(* Logix 5000 project; controller PDPMV1_60_v15 vendor 1 type 14 code 65 rev 15.1; software revision 15.00; part 2 of 3 *)
(* tags used below, declared in another part *)
   MVI69PDPMV1 : PDPMV1_ModuleDef;
(* MainProgram, continued *)

ROUTINE MainRoutine   (* ladder *)
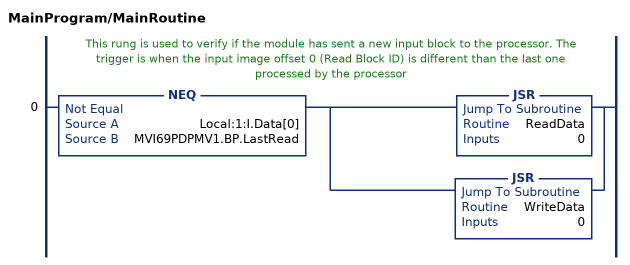
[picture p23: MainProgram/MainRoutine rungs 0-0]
   // This rung is used to verify if the module has sent a new input block to the processor. The trigger is when the input image offset 0 (Read Block ID) is different than the last one processed by the processor
   0: NEQ(Local:1:I.Data[0],MVI69PDPMV1.BP.LastRead)[JSR(ReadData,0) ,JSR(WriteData,0) ];
END_ROUTINE

ROUTINE ReadAlarm   (* ladder *)
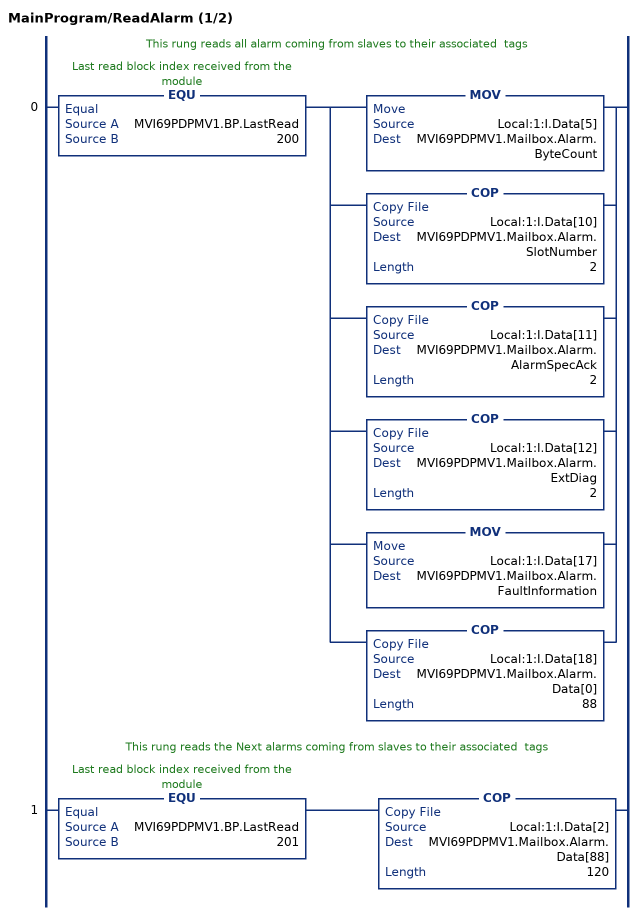
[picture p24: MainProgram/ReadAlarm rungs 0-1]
   // This rung reads all alarm coming from slaves to their associated  tags
   0: EQU(MVI69PDPMV1.BP.LastRead,200)[MOV(Local:1:I.Data[5],MVI69PDPMV1.Mailbox.Alarm.ByteCount) ,COP(Local:1:I.Data[10],MVI69PDPMV1.Mailbox.Alarm.SlotNumber,2) ,COP(Local:1:I.Data[11],MVI69PDPMV1.Mailbox.Alarm.AlarmSpecAck,2) ,COP(Local:1:I.Data[12],MVI69PDPMV1.Mailbox.Alarm.ExtDiag,2) ,MOV(Local:1:I.Data[17],MVI69PDPMV1.Mailbox.Alarm.FaultInformation) ,COP(Local:1:I.Data[18],MVI69PDPMV1.Mailbox.Alarm.Data[0],88) ];
   // This rung reads the Next alarms coming from slaves to their associated  tags
   1: EQU(MVI69PDPMV1.BP.LastRead,201)COP(Local:1:I.Data[2],MVI69PDPMV1.Mailbox.Alarm.Data[88],120);
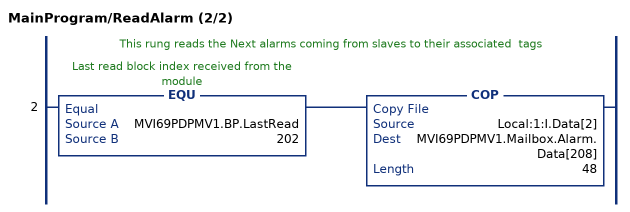
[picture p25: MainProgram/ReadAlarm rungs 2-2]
   // This rung reads the Next alarms coming from slaves to their associated  tags
   2: EQU(MVI69PDPMV1.BP.LastRead,202)COP(Local:1:I.Data[2],MVI69PDPMV1.Mailbox.Alarm.Data[208],48);
END_ROUTINE

ROUTINE ReadData   (* ladder *)
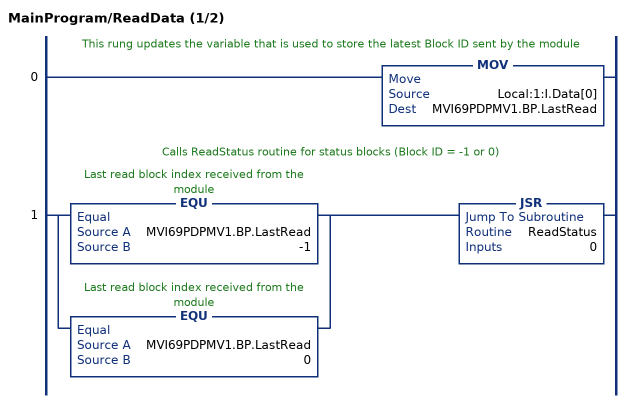
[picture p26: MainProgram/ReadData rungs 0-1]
   // This rung updates the variable that is used to store the latest Block ID sent by the module
   0: MOV(Local:1:I.Data[0],MVI69PDPMV1.BP.LastRead);
   // Calls ReadStatus routine for status blocks (Block ID = -1 or 0)
   1: [EQU(MVI69PDPMV1.BP.LastRead,-1) ,EQU(MVI69PDPMV1.BP.LastRead,0) ]JSR(ReadStatus,0);
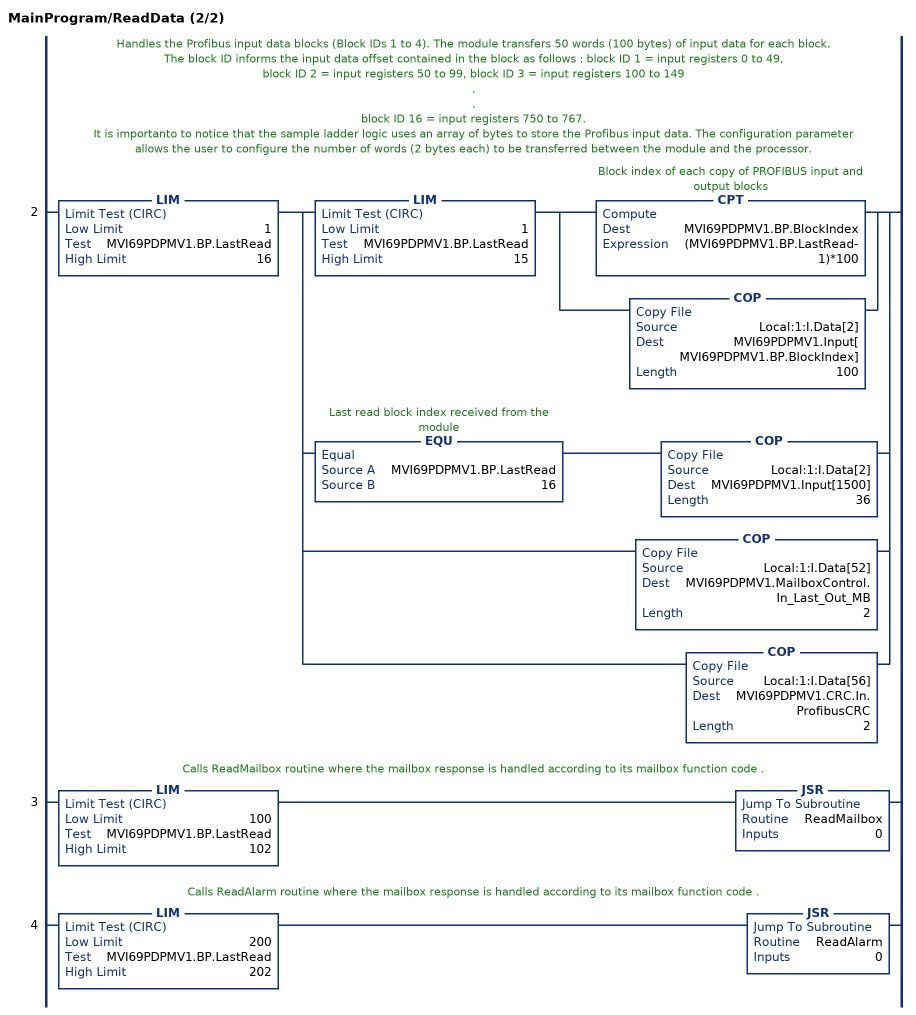
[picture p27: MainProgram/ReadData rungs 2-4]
   // Handles the Profibus input data blocks (Block IDs 1 to 4). The module transfers 50 words (100 bytes) of input data for each block.
   // The block ID informs the input data offset contained in the block as follows : block ID 1 = input registers 0 to 49,
   // block ID 2 = input registers 50 to 99, block ID 3 = input registers 100 to 149
   // .
   // .
   // block ID 16 = input registers 750 to 767.
   // It is importanto to notice that the sample ladder logic uses an array of bytes to store the Profibus input data. The configuration parameter allows the user to configure the number of words (2 bytes each) to be transferred between the module and the processor.
   2: LIM(1,MVI69PDPMV1.BP.LastRead,16)[LIM(1,MVI69PDPMV1.BP.LastRead,15) [CPT(MVI69PDPMV1.BP.BlockIndex,(MVI69PDPMV1.BP.LastRead-1)*100) ,COP(Local:1:I.Data[2],MVI69PDPMV1.Input[MVI69PDPMV1.BP.BlockIndex],100) ] ,EQU(MVI69PDPMV1.BP.LastRead,16) COP(Local:1:I.Data[2],MVI69PDPMV1.Input[1500],36) ,COP(Local:1:I.Data[52],MVI69PDPMV1.MailboxControl.In_Last_Out_MB,2) ,COP(Local:1:I.Data[56],MVI69PDPMV1.CRC.In.ProfibusCRC,2) ];
   // Calls ReadMailbox routine where the mailbox response is handled according to its mailbox function code .
   3: LIM(100,MVI69PDPMV1.BP.LastRead,102)JSR(ReadMailbox,0);
   // Calls ReadAlarm routine where the mailbox response is handled according to its mailbox function code .
   4: LIM(200,MVI69PDPMV1.BP.LastRead,202)JSR(ReadAlarm,0);
END_ROUTINE

ROUTINE ReadMailbox   (* ladder *)
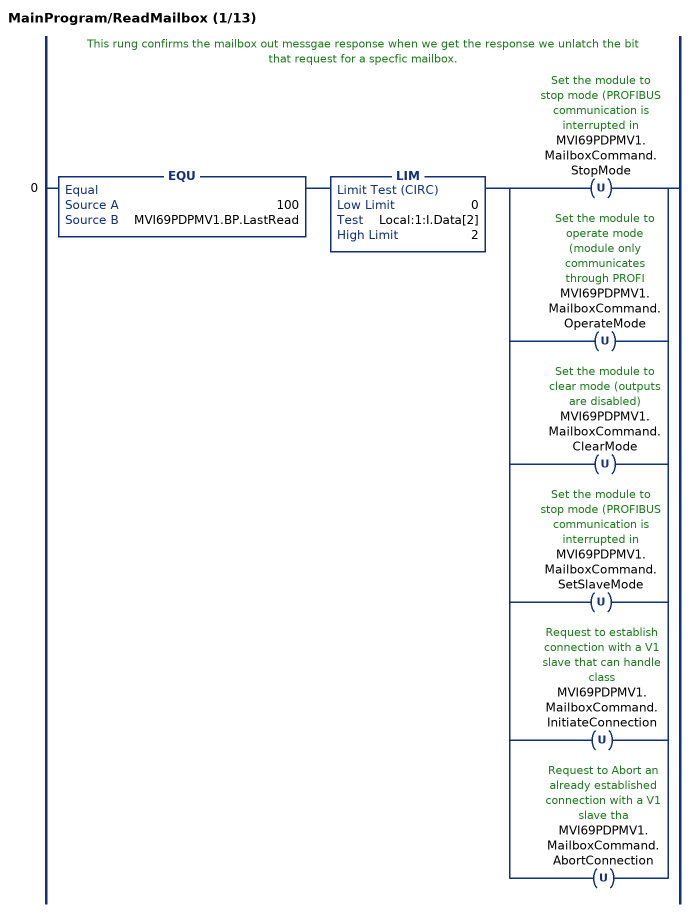
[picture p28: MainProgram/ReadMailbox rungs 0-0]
   // This rung confirms the mailbox out messgae response when we get the response we unlatch the bit that request for a specfic mailbox.
   0: EQU(100,MVI69PDPMV1.BP.LastRead)LIM(0,Local:1:I.Data[2],2)[OTU(MVI69PDPMV1.MailboxCommand.StopMode) ,OTU(MVI69PDPMV1.MailboxCommand.OperateMode) ,OTU(MVI69PDPMV1.MailboxCommand.ClearMode) ,OTU(MVI69PDPMV1.MailboxCommand.SetSlaveMode) ,OTU(MVI69PDPMV1.MailboxCommand.InitiateConnection) ,OTU(MVI69PDPMV1.MailboxCommand.AbortConnection) ];
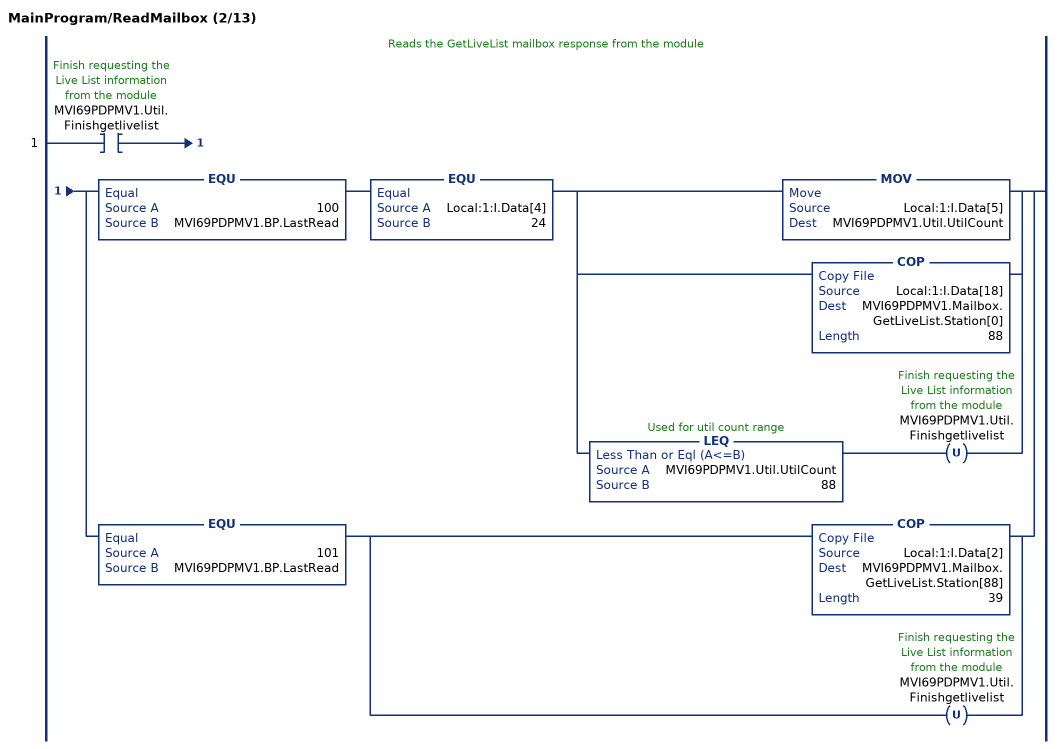
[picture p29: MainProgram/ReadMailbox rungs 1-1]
   // Reads the GetLiveList mailbox response from the module
   1: XIC(MVI69PDPMV1.Util.Finishgetlivelist)[EQU(100,MVI69PDPMV1.BP.LastRead) EQU(Local:1:I.Data[4],24) [MOV(Local:1:I.Data[5],MVI69PDPMV1.Util.UtilCount) ,COP(Local:1:I.Data[18],MVI69PDPMV1.Mailbox.GetLiveList.Station[0],88) ,LEQ(MVI69PDPMV1.Util.UtilCount,88) OTU(MVI69PDPMV1.Util.Finishgetlivelist) ] ,EQU(101,MVI69PDPMV1.BP.LastRead) [COP(Local:1:I.Data[2],MVI69PDPMV1.Mailbox.GetLiveList.Station[88],39) ,OTU(MVI69PDPMV1.Util.Finishgetlivelist) ] ];
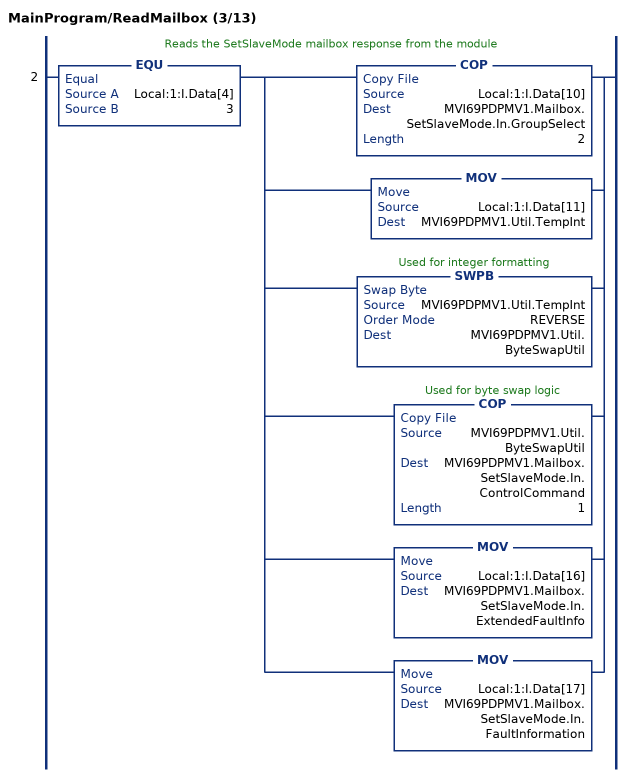
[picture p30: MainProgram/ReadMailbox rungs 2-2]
   // Reads the SetSlaveMode mailbox response from the module
   2: EQU(Local:1:I.Data[4],3)[COP(Local:1:I.Data[10],MVI69PDPMV1.Mailbox.SetSlaveMode.In.GroupSelect,2) ,MOV(Local:1:I.Data[11],MVI69PDPMV1.Util.TempInt) ,SWPB(MVI69PDPMV1.Util.TempInt,REVERSE,MVI69PDPMV1.Util.ByteSwapUtil) ,COP(MVI69PDPMV1.Util.ByteSwapUtil,MVI69PDPMV1.Mailbox.SetSlaveMode.In.ControlCommand,1) ,MOV(Local:1:I.Data[16],MVI69PDPMV1.Mailbox.SetSlaveMode.In.ExtendedFaultInfo) ,MOV(Local:1:I.Data[17],MVI69PDPMV1.Mailbox.SetSlaveMode.In.FaultInformation) ];
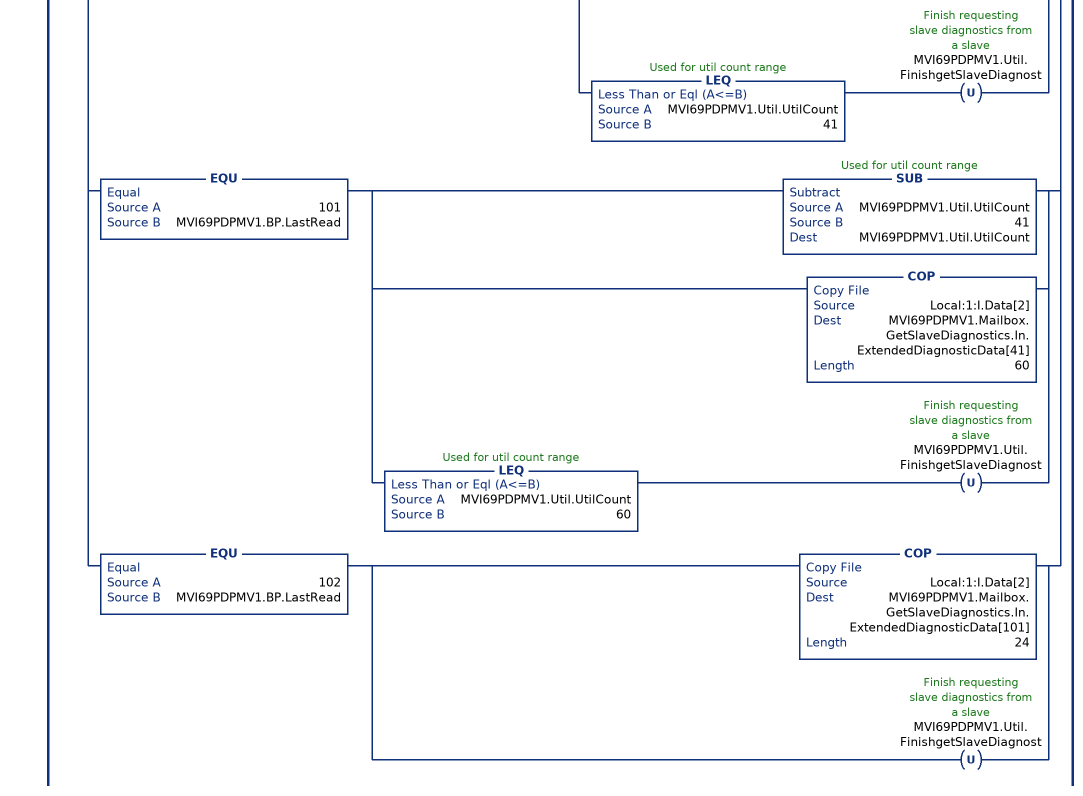
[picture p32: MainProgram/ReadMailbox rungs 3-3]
   // Reads the GetSlaveDiagnostics mailbox response from the module
   3: XIC(MVI69PDPMV1.Util.FinishgetSlaveDiagnost)[EQU(100,MVI69PDPMV1.BP.LastRead) EQU(Local:1:I.Data[4],4) [MOV(Local:1:I.Data[5],MVI69PDPMV1.Util.UtilCount) ,COP(Local:1:I.Data[10],MVI69PDPMV1.Mailbox.GetSlaveDiagnostics.In.RequestType,2) ,MOV(Local:1:I.Data[16],MVI69PDPMV1.Mailbox.GetSlaveDiagnostics.In.ExtendedFaultInfo) ,MOV(Local:1:I.Data[17],MVI69PDPMV1.Mailbox.GetSlaveDiagnostics.In.FaultInformation) ,MOV(Local:1:I.Data[18],MVI69PDPMV1.Mailbox.GetSlaveDiagnostics.In.StationStatus1_2) ,MOV(Local:1:I.Data[19],MVI69PDPMV1.Mailbox.GetSlaveDiagnostics.In.StationStatus3_4) ,MOV(Local:1:I.Data[20],MVI69PDPMV1.Mailbox.GetSlaveDiagnostics.In.IdentNumber) ,COP(Local:1:I.Data[21],MVI69PDPMV1.Mailbox.GetSlaveDiagnostics.In.ExtendedDiagnosticData[0],41) ,LEQ(MVI69PDPMV1.Util.UtilCount,41) OTU(MVI69PDPMV1.Util.FinishgetSlaveDiagnost) ] ,EQU(101,MVI69PDPMV1.BP.LastRead) [SUB(MVI69PDPMV1.Util.UtilCount,41,MVI69PDPMV1.Util.UtilCount) ,COP(Local:1:I.Data[2],MVI69PDPMV1.Mailbox.GetSlaveDiagnostics.In.ExtendedDiagnosticData[41],60) ,LEQ(MVI69PDPMV1.Util.UtilCount,60) OTU(MVI69PDPMV1.Util.FinishgetSlaveDiagnost) ] ,EQU(102,MVI69PDPMV1.BP.LastRead) [COP(Local:1:I.Data[2],MVI69PDPMV1.Mailbox.GetSlaveDiagnostics.In.ExtendedDiagnosticData[101],24) ,OTU(MVI69PDPMV1.Util.FinishgetSlaveDiagnost) ] ];
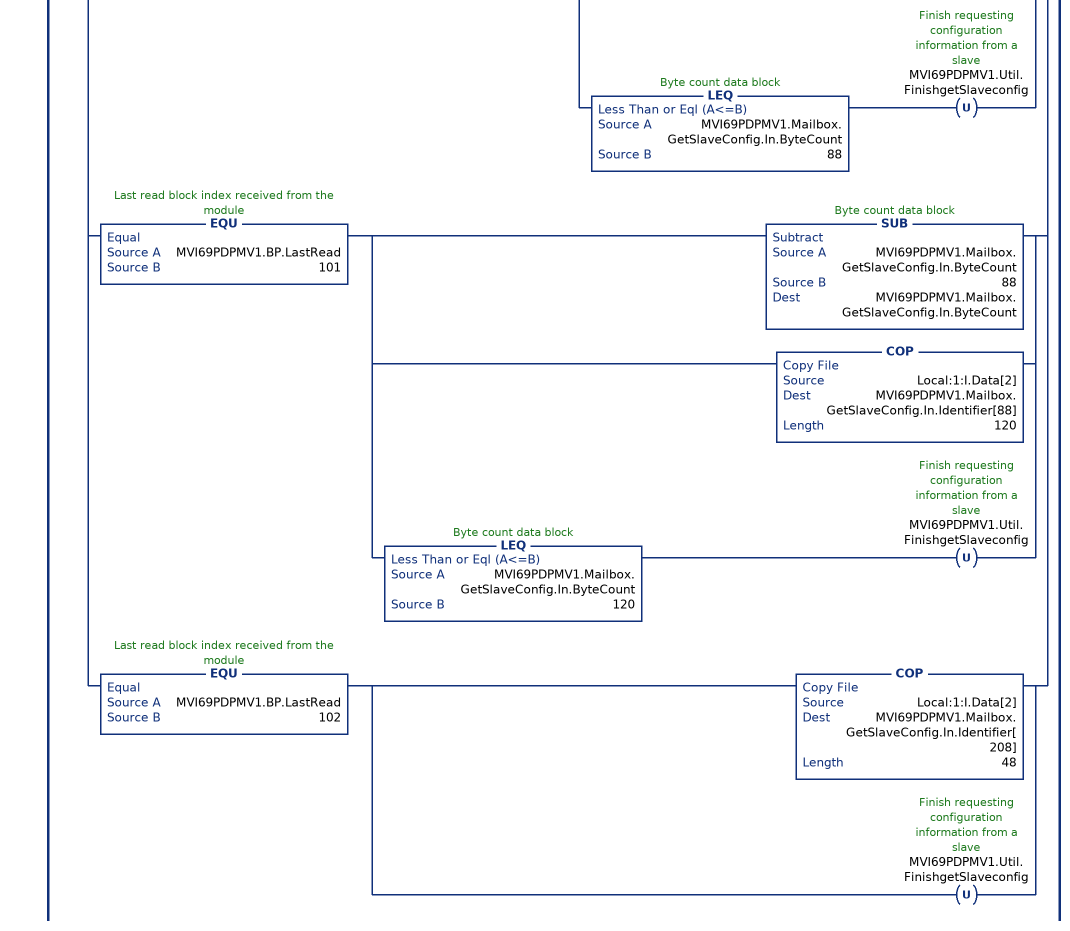
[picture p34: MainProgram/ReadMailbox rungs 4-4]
   // Reads the GetSlaveConfig mailbox response from the module
   4: XIC(MVI69PDPMV1.Util.FinishgetSlaveconfig)[EQU(MVI69PDPMV1.BP.LastRead,100) EQU(Local:1:I.Data[4],5) [MOV(Local:1:I.Data[5],MVI69PDPMV1.Mailbox.GetSlaveConfig.In.ByteCount) ,MOV(Local:1:I.Data[10],MVI69PDPMV1.Util.ByteSwapUtil) ,SWPB(MVI69PDPMV1.Util.ByteSwapUtil,REVERSE,MVI69PDPMV1.Mailbox.GetSlaveConfig.In.SlaveAddress) ,COP(Local:1:I.Data[14],MVI69PDPMV1.Mailbox.GetSlaveConfig.In.ErrorCode[0],2) ,MOV(Local:1:I.Data[16],MVI69PDPMV1.Mailbox.GetSlaveConfig.In.ReturnCode) ,MOV(Local:1:I.Data[17],MVI69PDPMV1.Mailbox.GetSlaveConfig.In.FaultInformation) ,COP(Local:1:I.Data[18],MVI69PDPMV1.Mailbox.GetSlaveConfig.In.Identifier[0],88) ,LEQ(MVI69PDPMV1.Mailbox.GetSlaveConfig.In.ByteCount,88) OTU(MVI69PDPMV1.Util.FinishgetSlaveconfig) ] ,EQU(MVI69PDPMV1.BP.LastRead,101) [SUB(MVI69PDPMV1.Mailbox.GetSlaveConfig.In.ByteCount,88,MVI69PDPMV1.Mailbox.GetSlaveConfig.In.ByteCount) ,COP(Local:1:I.Data[2],MVI69PDPMV1.Mailbox.GetSlaveConfig.In.Identifier[88],120) ,LEQ(MVI69PDPMV1.Mailbox.GetSlaveConfig.In.ByteCount,120) OTU(MVI69PDPMV1.Util.FinishgetSlaveconfig) ] ,EQU(MVI69PDPMV1.BP.LastRead,102) [COP(Local:1:I.Data[2],MVI69PDPMV1.Mailbox.GetSlaveConfig.In.Identifier[208],48) ,OTU(MVI69PDPMV1.Util.FinishgetSlaveconfig) ] ];
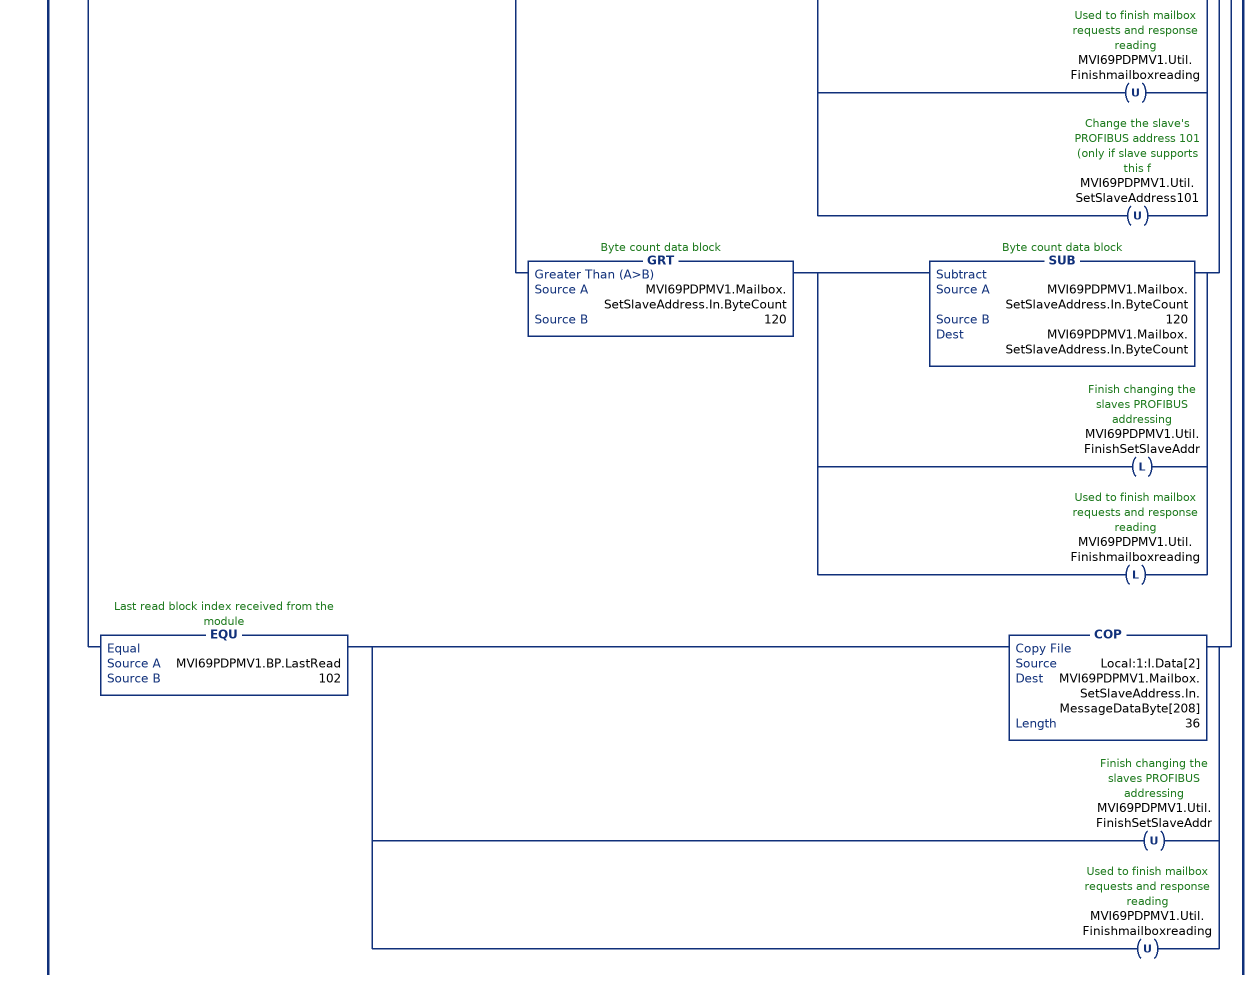
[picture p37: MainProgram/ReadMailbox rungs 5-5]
   // Reads the SetSlaveAddress mailbox response from the module
   5: XIC(MVI69PDPMV1.Util.FinishSetSlaveAddr)[EQU(MVI69PDPMV1.BP.LastRead,100) EQU(Local:1:I.Data[4],6) [MOV(Local:1:I.Data[5],MVI69PDPMV1.Mailbox.SetSlaveAddress.In.ByteCount) ,COP(Local:1:I.Data[10],MVI69PDPMV1.Mailbox.SetSlaveAddress.In.NewSlaveAddress,2) ,MOV(Local:1:I.Data[11],MVI69PDPMV1.Mailbox.SetSlaveAddress.In.SlaveIdentNumber) ,MOV(Local:1:I.Data[12],MVI69PDPMV1.Util.ByteSwapUtil) ,SWPB(MVI69PDPMV1.Util.ByteSwapUtil,REVERSE,MVI69PDPMV1.Mailbox.SetSlaveAddress.In.No_add_Chg) ,MOV(Local:1:I.Data[14],MVI69PDPMV1.Mailbox.SetSlaveAddress.In.ErrorCode1_2) ,MOV(Local:1:I.Data[15],MVI69PDPMV1.Mailbox.SetSlaveAddress.In.ErrorCode3_4) ,MOV(Local:1:I.Data[16],MVI69PDPMV1.Mailbox.SetSlaveAddress.In.ReturnCode) ,MOV(Local:1:I.Data[17],MVI69PDPMV1.Mailbox.SetSlaveAddress.In.FaultInformation) ,COP(Local:1:I.Data[18],MVI69PDPMV1.Mailbox.SetSlaveAddress.In.MessageDataByte[0],88) ,LEQ(MVI69PDPMV1.Mailbox.SetSlaveAddress.In.ByteCount,88) OTU(MVI69PDPMV1.Util.FinishSetSlaveAddr) ,GRT(MVI69PDPMV1.Mailbox.SetSlaveAddress.In.ByteCount,88) [SUB(MVI69PDPMV1.Mailbox.SetSlaveAddress.In.ByteCount,88,MVI69PDPMV1.Mailbox.SetSlaveAddress.In.ByteCount) ,OTL(MVI69PDPMV1.Util.SetSlaveAddress101) ,OTL(MVI69PDPMV1.Util.Finishmailboxreading) ] ] ,EQU(MVI69PDPMV1.BP.LastRead,101) XIC(MVI69PDPMV1.Util.Finishmailboxreading) [LEQ(MVI69PDPMV1.Mailbox.SetSlaveAddress.In.ByteCount,120) [COP(Local:1:I.Data[2],MVI69PDPMV1.Mailbox.SetSlaveAddress.In.MessageDataByte[88],120) ,OTU(MVI69PDPMV1.Util.Finishmailboxreading) ,OTU(MVI69PDPMV1.Util.SetSlaveAddress101) ] ,GRT(MVI69PDPMV1.Mailbox.SetSlaveAddress.In.ByteCount,120) [SUB(MVI69PDPMV1.Mailbox.SetSlaveAddress.In.ByteCount,120,MVI69PDPMV1.Mailbox.SetSlaveAddress.In.ByteCount) ,OTL(MVI69PDPMV1.Util.FinishSetSlaveAddr) ,OTL(MVI69PDPMV1.Util.Finishmailboxreading) ] ] ,EQU(MVI69PDPMV1.BP.LastRead,102) [COP(Local:1:I.Data[2],MVI69PDPMV1.Mailbox.SetSlaveAddress.In.MessageDataByte[208],36) ,OTU(MVI69PDPMV1.Util.FinishSetSlaveAddr) ,OTU(MVI69PDPMV1.Util.Finishmailboxreading) ] ];
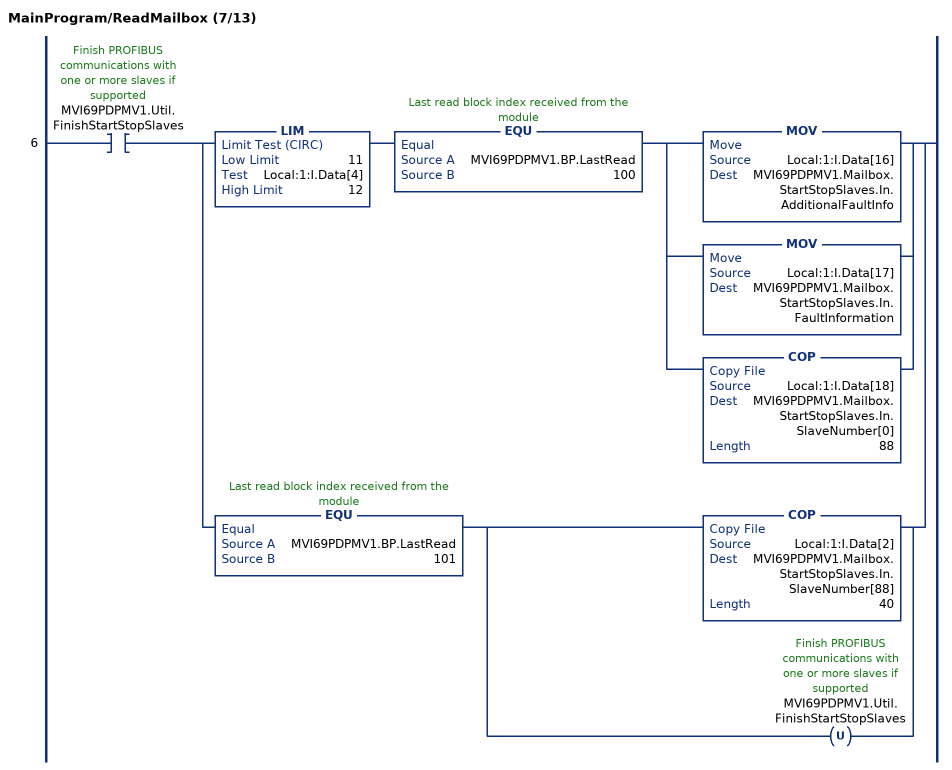
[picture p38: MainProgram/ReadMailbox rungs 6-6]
   6: XIC(MVI69PDPMV1.Util.FinishStartStopSlaves)[LIM(11,Local:1:I.Data[4],12) EQU(MVI69PDPMV1.BP.LastRead,100) [MOV(Local:1:I.Data[16],MVI69PDPMV1.Mailbox.StartStopSlaves.In.AdditionalFaultInfo) ,MOV(Local:1:I.Data[17],MVI69PDPMV1.Mailbox.StartStopSlaves.In.FaultInformation) ,COP(Local:1:I.Data[18],MVI69PDPMV1.Mailbox.StartStopSlaves.In.SlaveNumber[0],88) ] ,EQU(MVI69PDPMV1.BP.LastRead,101) [COP(Local:1:I.Data[2],MVI69PDPMV1.Mailbox.StartStopSlaves.In.SlaveNumber[88],40) ,OTU(MVI69PDPMV1.Util.FinishStartStopSlaves) ] ];
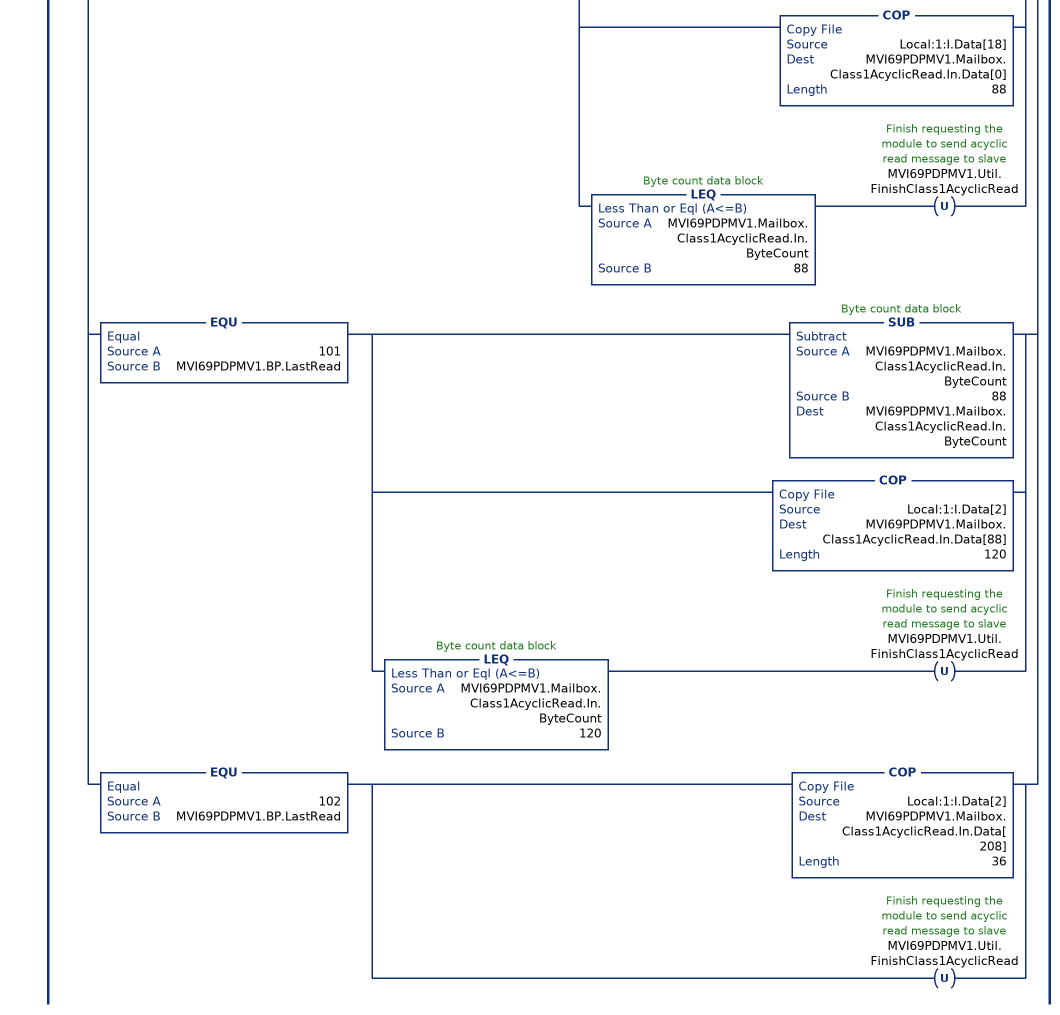
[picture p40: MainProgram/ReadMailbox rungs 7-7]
   // Reads the AcyclicRead mailbox response from the module
   7: XIC(MVI69PDPMV1.Util.FinishClass1AcyclicRead)[EQU(100,MVI69PDPMV1.BP.LastRead) EQU(Local:1:I.Data[4],32) [MOV(Local:1:I.Data[5],MVI69PDPMV1.Mailbox.Class1AcyclicRead.In.ByteCount) ,COP(Local:1:I.Data[10],MVI69PDPMV1.Mailbox.Class1AcyclicRead.In.SlotNumber,2) ,COP(Local:1:I.Data[11],MVI69PDPMV1.Mailbox.Class1AcyclicRead.In.Length,2) ,COP(Local:1:I.Data[14],MVI69PDPMV1.Mailbox.Class1AcyclicRead.In.ErrorDecode,1) ,COP(Local:1:I.Data[15],MVI69PDPMV1.Mailbox.Class1AcyclicRead.In.ErrorCode2,2) ,MOV(Local:1:I.Data[16],MVI69PDPMV1.Mailbox.Class1AcyclicRead.In.ExtendedFaultInfo) ,MOV(Local:1:I.Data[17],MVI69PDPMV1.Mailbox.Class1AcyclicRead.In.FaultInformation) ,COP(Local:1:I.Data[18],MVI69PDPMV1.Mailbox.Class1AcyclicRead.In.Data[0],88) ,LEQ(MVI69PDPMV1.Mailbox.Class1AcyclicRead.In.ByteCount,88) OTU(MVI69PDPMV1.Util.FinishClass1AcyclicRead) ] ,EQU(101,MVI69PDPMV1.BP.LastRead) [SUB(MVI69PDPMV1.Mailbox.Class1AcyclicRead.In.ByteCount,88,MVI69PDPMV1.Mailbox.Class1AcyclicRead.In.ByteCount) ,COP(Local:1:I.Data[2],MVI69PDPMV1.Mailbox.Class1AcyclicRead.In.Data[88],120) ,LEQ(MVI69PDPMV1.Mailbox.Class1AcyclicRead.In.ByteCount,120) OTU(MVI69PDPMV1.Util.FinishClass1AcyclicRead) ] ,EQU(102,MVI69PDPMV1.BP.LastRead) [COP(Local:1:I.Data[2],MVI69PDPMV1.Mailbox.Class1AcyclicRead.In.Data[208],36) ,OTU(MVI69PDPMV1.Util.FinishClass1AcyclicRead) ] ];
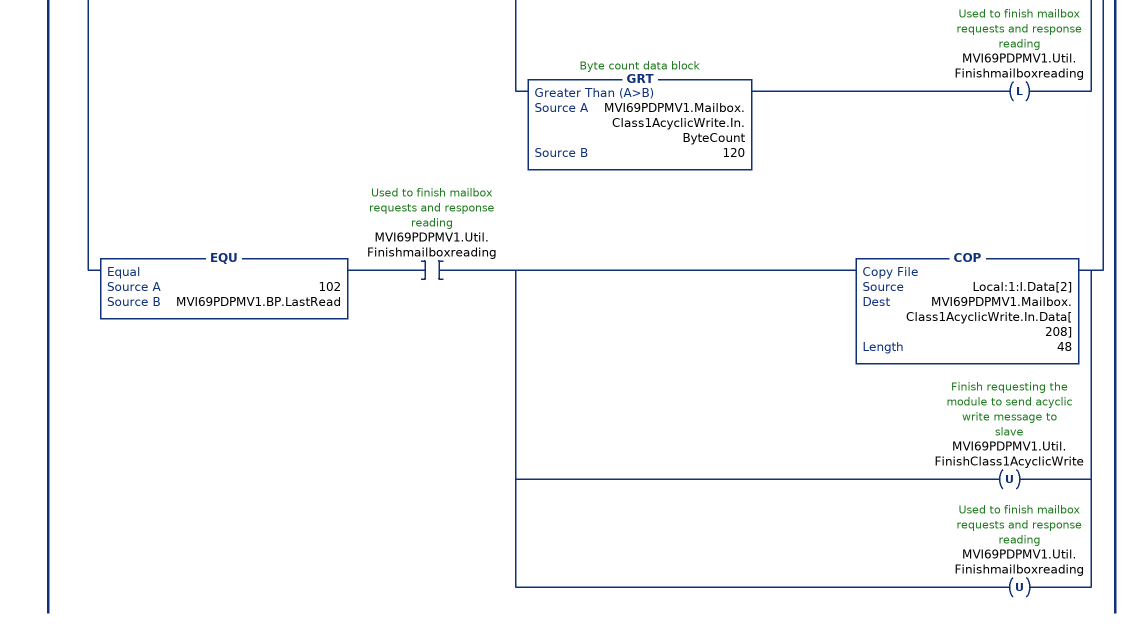
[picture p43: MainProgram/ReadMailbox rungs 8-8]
   // Reads the AcyclicWrite mailbox response from the module
   8: XIC(MVI69PDPMV1.Util.FinishClass1AcyclicWrite)[EQU(100,MVI69PDPMV1.BP.LastRead) EQU(Local:1:I.Data[4],33) [MOV(Local:1:I.Data[5],MVI69PDPMV1.Mailbox.Class1AcyclicWrite.In.ByteCount) ,COP(Local:1:I.Data[10],MVI69PDPMV1.Mailbox.Class1AcyclicWrite.In.SlotNumber,2) ,COP(Local:1:I.Data[11],MVI69PDPMV1.Mailbox.Class1AcyclicWrite.In.Length,2) ,COP(Local:1:I.Data[14],MVI69PDPMV1.Mailbox.Class1AcyclicWrite.In.ErrorDecode,1) ,COP(Local:1:I.Data[15],MVI69PDPMV1.Mailbox.Class1AcyclicWrite.In.ErrorCode2,2) ,MOV(Local:1:I.Data[16],MVI69PDPMV1.Mailbox.Class1AcyclicWrite.In.ExtendedFaultInfo) ,MOV(Local:1:I.Data[17],MVI69PDPMV1.Mailbox.Class1AcyclicWrite.In.FaultInformation) ,COP(Local:1:I.Data[18],MVI69PDPMV1.Mailbox.Class1AcyclicWrite.In.Data[0],88) ,LEQ(MVI69PDPMV1.Mailbox.Class1AcyclicWrite.In.ByteCount,88) OTU(MVI69PDPMV1.Util.FinishClass1AcyclicWrite) ,GRT(MVI69PDPMV1.Mailbox.Class1AcyclicWrite.In.ByteCount,88) OTL(MVI69PDPMV1.Util.Finishmailboxreading) ] ,EQU(101,MVI69PDPMV1.BP.LastRead) XIC(MVI69PDPMV1.Util.Finishmailboxreading) [LES(MVI69PDPMV1.Mailbox.Class1AcyclicWrite.In.ByteCount,120) [COP(Local:1:I.Data[2],MVI69PDPMV1.Mailbox.Class1AcyclicWrite.In.Data[88],120) ,OTU(MVI69PDPMV1.Util.FinishClass1AcyclicWrite) ,OTU(MVI69PDPMV1.Util.Finishmailboxreading) ,OTU(MVI69PDPMV1.Util.Class1AcyclicWrite101) ] ,GRT(MVI69PDPMV1.Mailbox.Class1AcyclicWrite.In.ByteCount,120) OTL(MVI69PDPMV1.Util.Finishmailboxreading) ] ,EQU(102,MVI69PDPMV1.BP.LastRead) XIC(MVI69PDPMV1.Util.Finishmailboxreading) [COP(Local:1:I.Data[2],MVI69PDPMV1.Mailbox.Class1AcyclicWrite.In.Data[208],48) ,OTU(MVI69PDPMV1.Util.FinishClass1AcyclicWrite) ,OTU(MVI69PDPMV1.Util.Finishmailboxreading) ] ];
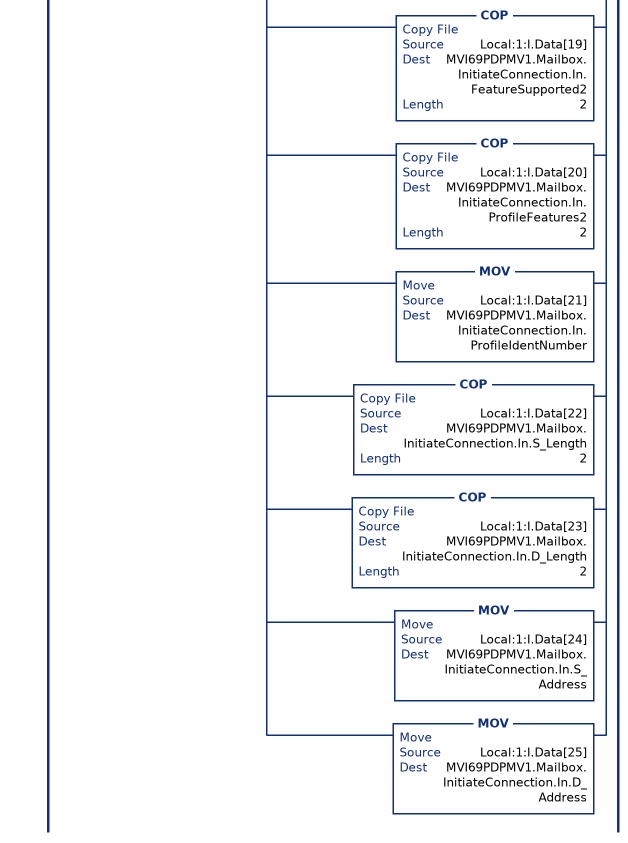
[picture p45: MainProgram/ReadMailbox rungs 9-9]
   // Reads the Initiate connection mailbox response from the module
   9: EQU(Local:1:I.Data[4],37)[MOV(Local:1:I.Data[5],MVI69PDPMV1.Mailbox.InitiateConnection.In.SizeofdatainBytes) ,MOV(Local:1:I.Data[10],MVI69PDPMV1.Mailbox.InitiateConnection.In.C_REF) ,COP(Local:1:I.Data[11],MVI69PDPMV1.Mailbox.InitiateConnection.In.MaxDataLength,2) ,MOV(Local:1:I.Data[12],MVI69PDPMV1.Mailbox.InitiateConnection.In.MinmumSlaveTimeout) ,COP(Local:1:I.Data[14],MVI69PDPMV1.Mailbox.InitiateConnection.In.ErrorDecode,1) ,COP(Local:1:I.Data[15],MVI69PDPMV1.Mailbox.InitiateConnection.In.ErrorCode2,2) ,MOV(Local:1:I.Data[16],MVI69PDPMV1.Mailbox.InitiateConnection.In.ExtendedFaultInformation) ,MOV(Local:1:I.Data[17],MVI69PDPMV1.Mailbox.InitiateConnection.In.FaultInformation) ,MOV(Local:1:I.Data[18],MVI69PDPMV1.Mailbox.InitiateConnection.In.SendTimeout) ,COP(Local:1:I.Data[19],MVI69PDPMV1.Mailbox.InitiateConnection.In.FeatureSupported2,2) ,COP(Local:1:I.Data[20],MVI69PDPMV1.Mailbox.InitiateConnection.In.ProfileFeatures2,2) ,MOV(Local:1:I.Data[21],MVI69PDPMV1.Mailbox.InitiateConnection.In.ProfileIdentNumber) ,COP(Local:1:I.Data[22],MVI69PDPMV1.Mailbox.InitiateConnection.In.S_Length,2) ,COP(Local:1:I.Data[23],MVI69PDPMV1.Mailbox.InitiateConnection.In.D_Length,2) ,MOV(Local:1:I.Data[24],MVI69PDPMV1.Mailbox.InitiateConnection.In.S_Address) ,MOV(Local:1:I.Data[25],MVI69PDPMV1.Mailbox.InitiateConnection.In.D_Address) ];
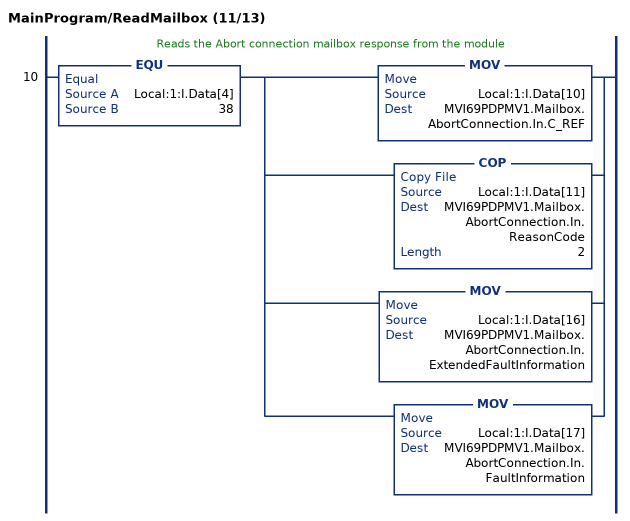
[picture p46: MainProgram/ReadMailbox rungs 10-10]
   // Reads the Abort connection mailbox response from the module
   10: EQU(Local:1:I.Data[4],38)[MOV(Local:1:I.Data[10],MVI69PDPMV1.Mailbox.AbortConnection.In.C_REF) ,COP(Local:1:I.Data[11],MVI69PDPMV1.Mailbox.AbortConnection.In.ReasonCode,2) ,MOV(Local:1:I.Data[16],MVI69PDPMV1.Mailbox.AbortConnection.In.ExtendedFaultInformation) ,MOV(Local:1:I.Data[17],MVI69PDPMV1.Mailbox.AbortConnection.In.FaultInformation) ];
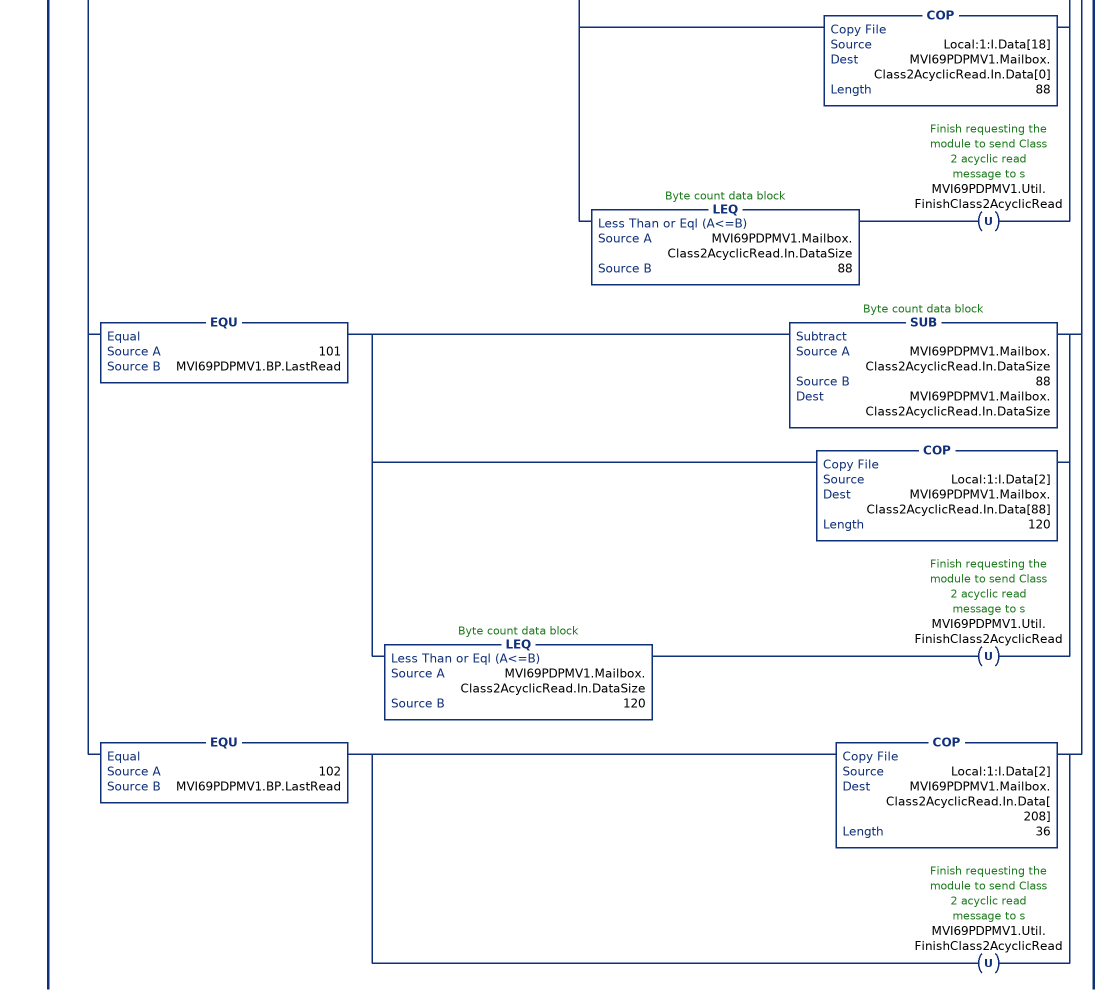
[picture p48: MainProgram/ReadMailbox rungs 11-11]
   // Reads the Class2 AcyclicRead mailbox response from the module
   11: XIC(MVI69PDPMV1.Util.FinishClass2AcyclicRead)[EQU(100,MVI69PDPMV1.BP.LastRead) EQU(Local:1:I.Data[4],39) [MOV(Local:1:I.Data[5],MVI69PDPMV1.Mailbox.Class2AcyclicRead.In.DataSize) ,MOV(Local:1:I.Data[10],MVI69PDPMV1.Mailbox.Class2AcyclicRead.In.C_REF) ,COP(Local:1:I.Data[11],MVI69PDPMV1.Mailbox.Class2AcyclicRead.In.Index,2) ,COP(Local:1:I.Data[12],MVI69PDPMV1.Mailbox.Class2AcyclicRead.In.Length,2) ,COP(Local:1:I.Data[14],MVI69PDPMV1.Mailbox.Class2AcyclicRead.In.ErrorDecode,1) ,COP(Local:1:I.Data[15],MVI69PDPMV1.Mailbox.Class2AcyclicRead.In.ErrorCode2,2) ,MOV(Local:1:I.Data[16],MVI69PDPMV1.Mailbox.Class2AcyclicRead.In.ExtendedFaultInfo) ,MOV(Local:1:I.Data[17],MVI69PDPMV1.Mailbox.Class2AcyclicRead.In.FaultInformation) ,COP(Local:1:I.Data[18],MVI69PDPMV1.Mailbox.Class2AcyclicRead.In.Data[0],88) ,LEQ(MVI69PDPMV1.Mailbox.Class2AcyclicRead.In.DataSize,88) OTU(MVI69PDPMV1.Util.FinishClass2AcyclicRead) ] ,EQU(101,MVI69PDPMV1.BP.LastRead) [SUB(MVI69PDPMV1.Mailbox.Class2AcyclicRead.In.DataSize,88,MVI69PDPMV1.Mailbox.Class2AcyclicRead.In.DataSize) ,COP(Local:1:I.Data[2],MVI69PDPMV1.Mailbox.Class2AcyclicRead.In.Data[88],120) ,LEQ(MVI69PDPMV1.Mailbox.Class2AcyclicRead.In.DataSize,120) OTU(MVI69PDPMV1.Util.FinishClass2AcyclicRead) ] ,EQU(102,MVI69PDPMV1.BP.LastRead) [COP(Local:1:I.Data[2],MVI69PDPMV1.Mailbox.Class2AcyclicRead.In.Data[208],36) ,OTU(MVI69PDPMV1.Util.FinishClass2AcyclicRead) ] ];
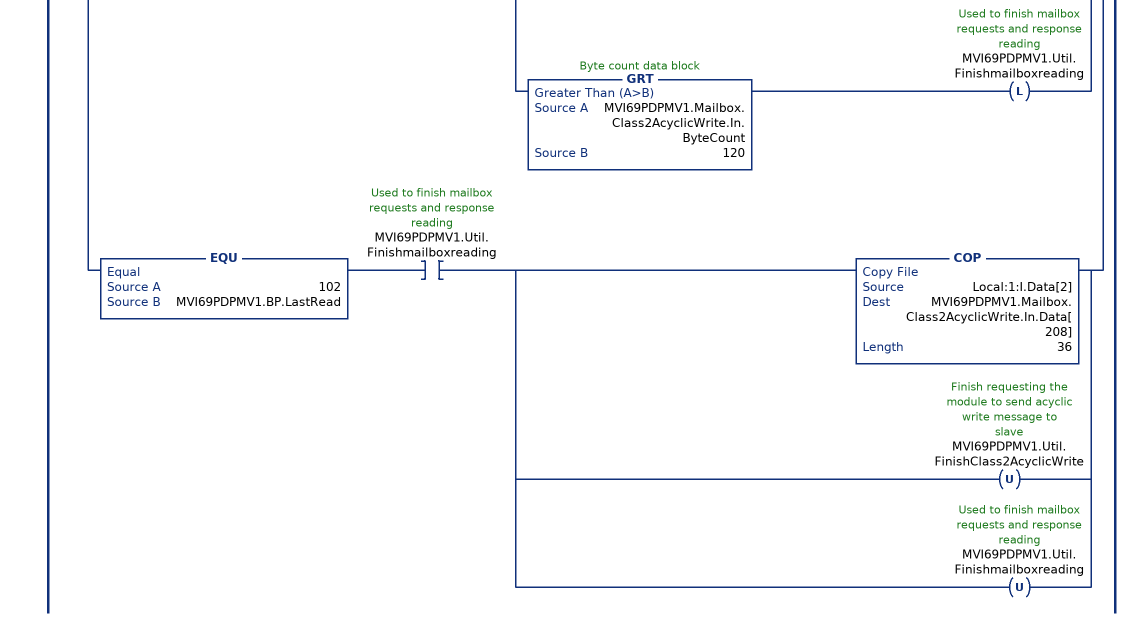
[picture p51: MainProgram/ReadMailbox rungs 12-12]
   // Reads the AcyclicWrite mailbox response from the module
   12: XIC(MVI69PDPMV1.Util.FinishClass2AcyclicWrite)[EQU(100,MVI69PDPMV1.BP.LastRead) EQU(Local:1:I.Data[4],40) [MOV(Local:1:I.Data[5],MVI69PDPMV1.Mailbox.Class2AcyclicWrite.In.ByteCount) ,MOV(Local:1:I.Data[10],MVI69PDPMV1.Mailbox.Class2AcyclicWrite.In.C_REF) ,COP(Local:1:I.Data[11],MVI69PDPMV1.Mailbox.Class2AcyclicWrite.In.Index,2) ,COP(Local:1:I.Data[12],MVI69PDPMV1.Mailbox.Class2AcyclicWrite.In.Length,1) ,COP(Local:1:I.Data[14],MVI69PDPMV1.Mailbox.Class2AcyclicWrite.In.ErrorDecode,1) ,COP(Local:1:I.Data[15],MVI69PDPMV1.Mailbox.Class2AcyclicWrite.In.ErrorCode2,2) ,MOV(Local:1:I.Data[16],MVI69PDPMV1.Mailbox.Class2AcyclicWrite.In.ExtendedFaultInfo) ,MOV(Local:1:I.Data[17],MVI69PDPMV1.Mailbox.Class2AcyclicWrite.In.FaultInformation) ,COP(Local:1:I.Data[18],MVI69PDPMV1.Mailbox.Class2AcyclicWrite.In.Data[0],88) ,LEQ(MVI69PDPMV1.Mailbox.Class2AcyclicWrite.In.ByteCount,88) OTU(MVI69PDPMV1.Util.FinishClass2AcyclicWrite) ,GRT(MVI69PDPMV1.Mailbox.Class2AcyclicWrite.In.ByteCount,88) OTL(MVI69PDPMV1.Util.Finishmailboxreading) ] ,EQU(101,MVI69PDPMV1.BP.LastRead) XIC(MVI69PDPMV1.Util.Finishmailboxreading) [LES(MVI69PDPMV1.Mailbox.Class2AcyclicWrite.In.ByteCount,120) [COP(Local:1:I.Data[2],MVI69PDPMV1.Mailbox.Class2AcyclicWrite.In.Data[88],120) ,OTU(MVI69PDPMV1.Util.FinishClass2AcyclicWrite) ,OTU(MVI69PDPMV1.Util.Finishmailboxreading) ,OTU(MVI69PDPMV1.Util.Class2AcyclicWrite101) ] ,GRT(MVI69PDPMV1.Mailbox.Class2AcyclicWrite.In.ByteCount,120) OTL(MVI69PDPMV1.Util.Finishmailboxreading) ] ,EQU(102,MVI69PDPMV1.BP.LastRead) XIC(MVI69PDPMV1.Util.Finishmailboxreading) [COP(Local:1:I.Data[2],MVI69PDPMV1.Mailbox.Class2AcyclicWrite.In.Data[208],36) ,OTU(MVI69PDPMV1.Util.FinishClass2AcyclicWrite) ,OTU(MVI69PDPMV1.Util.Finishmailboxreading) ] ];
END_ROUTINE
